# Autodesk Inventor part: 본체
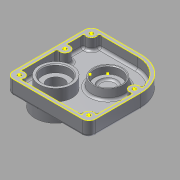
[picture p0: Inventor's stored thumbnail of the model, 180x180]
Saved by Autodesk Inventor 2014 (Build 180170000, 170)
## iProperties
Created: 2015-10
Part Number: 본체
Material: 알루미늄 6061
Document SubType Name: Modeling
Designer: youjin16
Density: 2.71 g/cm^3
Appearance: 알루미늄 - 평지
Mass: 265.675 g
Surface Area: 404.309 cm^2
Volume: 98.0352 cm^3
Author: youjin16
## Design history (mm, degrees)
sketch "스케치1"
  geometry: L1 (-42, 51.5)-(50, 51.5); L2 (50, 51.5)-(50, -43.5); L3 (42, -51.5)-(-42, -51.5); L4 (-50, -43.5)-(-50, 43.5); L5 (-50, 51.5)-(50, -51.5); L6 (50, 51.5)-(-50, -51.5); A1 r 8 centre (-42, 43.5) between (-42, 51.5) and (-50, 43.5); A2 r 8 centre (-42, -43.5) between (-50, -43.5) and (-42, -51.5); A3 r 8 centre (42, -43.5) between (42, -51.5) and (50, -43.5); 1 further point
  constraints: 12 end point, 6 point on circle, 6 point on line, 6 tangent, 3 centre point, 2 equal radius, 2 midpoint, 2 parallel, 1 horizontal, 1 perpendicular
  dimensions: "d0" = 100 distance of L5.end L6.end; "d1" = 103 distance of L6.end L5.start; "d2" = 8 radius of A1
extrude "돌출1" new body sketch "스케치1" distance "d3" = 18; taper "d4" = 0 deg
sketch "스케치2"
  geometry: L1 (50, 51.5)-(-42, 51.5) reference; L2 (-50, 43.5)-(-50, -43.5) reference; L3 (-42, -51.5)-(42, -51.5) reference; L4 (50, -43.5)-(50, 51.5) reference; L5 (-37.528, -47.5)-(37.528, -47.5); L6 (-46, -39.028)-(-46, 39.028); L7 (46, -39.028)-(46, 51.5); L8 (-37.528, 47.5)-(46, 47.5); L9 (-42, 17.5)-(-46, 17.5); L10 (-42, 5.5)-(-46, 5.5); L11 (42, 5.5)-(46, 5.5); L12 (42, 17.5)-(46, 17.5); A1 r 8 centre (-42, 43.5) between (-42, 51.5) and (-50, 43.5) reference; A2 r 8 centre (-42, -43.5) between (-50, -43.5) and (-42, -51.5) reference; A3 r 8 centre (42, -43.5) between (42, -51.5) and (50, -43.5) reference; A4 r 6 centre (-42, 43.5) between (-46, 39.028) and (-37.528, 47.5); A5 r 6 centre (-42, -43.5) between (-46, -39.028) and (-37.528, -47.5); A6 r 6 centre (42, -43.5) between (37.528, -47.5) and (46, -39.028); A7 r 6 centre (-42, 11.5) between (-42, 17.5) and (-42, 5.5); A8 r 6 centre (42, 11.5) between (42, 5.5) and (42, 17.5); 1 further point
  constraints: 16 end point, 10 point on circle, 6 perpendicular, 6 point on line, 5 centre point, 4 tangent, 3 coincident, 2 parallel, 2 vertical alignment
  dimensions: "d5" = 12 diameter of A4; "d6" = 12 diameter of A5; "d7" = 12 diameter of A6; "d8" = 4 distance between parallel lines of L3 L5; "d9" = 4 distance between parallel lines of L2 L6; "d10" = 4 distance between parallel lines of L8 L1; "d11" = 4 distance between parallel lines of L4 L7; "d16" = 12 diameter of A7; "d17" = 63 distance from line of L3 A7.centre; "d18" = 12 diameter of A8; "d19" = 63 distance from line of L3 A8.centre
extrude "돌출2" cut sketch "스케치2" distance "d12" = 4; taper "d13" = 0 deg
extrude "돌출3" join sketch "스케치2" stored distance "d20" = 4; taper "d21" = 0 deg
extrude "돌출4" join sketch "스케치2" distance "d22" = 4; taper "d23" = 0 deg
extrude "돌출5" join sketch "스케치2" distance "d24" = 4; taper "d25" = 0 deg
fillet "모깎기1" dims "d31" = 40
sketch "스케치5"
  geometry: L1 (46, 28.936)-(46, 17.5) reference; L2 (46, 17.5)-(42, 17.5) reference; L3 (42, 5.5)-(46, 5.5) reference; L4 (-37.528, 47.5)-(27.436, 47.5) reference; L5 (10, 51.5)-(-42, 51.5) reference; A1 r 6 centre (42, 11.5) between (42, 17.5) and (42, 5.5) reference; A2 r 40 centre (10, 11.5) between (27.436, 47.5) and (10, 51.5) reference; A3 r 36 centre (10, 11.5) between (10, 47.5) and (45.496, 5.5); A4 r 40 centre (10, 11.5) between (10, 51.5) and (46, 28.936); A5 r 36 centre (10, 11.5) between (45.496, 17.5) and (10, 47.5); A6 r 40 centre (10, 11.5) between (27.436, 47.5) and (10, 51.5); A7 r 40 centre (10, 11.5) between (46, 28.936) and (27.436, 47.5); A8 r 36 centre (10, 11.5) between (45.496, 5.5) and (45.688, 16.233); A9 r 36 centre (10, 11.5) between (45.688, 16.233) and (45.496, 17.5); 1 further point
  constraints: 15 point on circle, 7 centre point, 3 end point, 3 point on line, 2 coincident
  dimensions: "d32" = 72 diameter of A3
extrude "돌출7" join sketch "스케치5" stored distance "d33" = 10; taper "d34" = 0 deg
sketch "스케치6"
  geometry: C1 r 4 at (42, 43.5); C2 r 4 at (42, 11.5); C3 r 4 at (42, -43.5); C4 r 4 at (-42, -43.5); C5 r 4 at (-42, 11.5); A1 r 6 centre (42, 43.5) between (37.528, 47.5) and (46, 39.028) reference; A2 r 6 centre (42, -43.5) between (46, -39.028) and (37.528, -47.5) reference; A3 r 6 centre (42, 11.5) between (42, 17.5) and (42, 5.5) reference; A4 r 6 centre (-42, -43.5) between (-37.528, -47.5) and (-46, -39.028) reference; A5 r 6 centre (-42, 11.5) between (-42, 5.5) and (-42, 17.5) reference; 1 further point
  constraints: 5 centre point, 5 coincident
  dimensions: "d35" = 8 diameter of C1; "d36" = 8 diameter of C2; "d37" = 8 diameter of C3; "d38" = 8 diameter of C4; "d39" = 8 diameter of C5
extrude "돌출8" cut sketch "스케치6" distance "d40" = 4.4; taper "d41" = 0 deg
sketch "스케치7"
  geometry: C1 r 4 at (0, 0) reference; C2 r 4 at (0, 55) reference; C3 r 4 at (0, 87) reference; C4 r 4 at (-84, 55) reference; C5 r 4 at (-84, 0) reference; C6 r 2.25 at (0, 0); C7 r 2.25 at (0, 55); C8 r 2.25 at (0, 87); C9 r 2.25 at (-84, 55); C10 r 2.25 at (-84, 0); 1 further point
  constraints: 5 centre point, 5 coincident
  dimensions: "d42" = 4.5 diameter of C6; "d43" = 4.5 diameter of C7; "d44" = 4.5 diameter of C8; "d45" = 4.5 diameter of C9; "d46" = 4.5 diameter of C10
extrude "돌출9" cut sketch "스케치7" stored distance "d47" = 4.4; taper "d48" = 0 deg
sketch "스케치8"
  geometry: L1 (10, 51.5)-(-42, 51.5) reference; L2 (-50, 43.5)-(-50, -43.5) reference; L3 (-42, -51.5)-(42, -51.5) reference; L4 (50, -43.5)-(50, 11.5) reference; L5 (45.496, 17.5)-(42, 17.5) reference; L6 (42, 5.5)-(46, 5.5) reference; L7 (46, 5.5)-(46, -39.028) reference; L8 (37.528, -47.5)-(-37.528, -47.5) reference; L9 (-46, -39.028)-(-46, 5.5) reference; L10 (-46, 5.5)-(-42, 5.5) reference; L11 (-42, 17.5)-(-46, 17.5) reference; L12 (-46, 17.5)-(-46, 39.028) reference; L13 (-37.528, 47.5)-(10, 47.5) reference; C1 r 2.25 at (42, 11.5) reference; C2 r 2.25 at (-42, 11.5) reference; C3 r 2.25 at (-42, -43.5) reference; C4 r 2.25 at (-42, 43.5) reference; C5 r 2.25 at (42, -43.5) reference; A1 r 40 centre (10, 11.5) between (50, 11.5) and (10, 51.5) reference; A2 r 8 centre (-42, 43.5) between (-42, 51.5) and (-50, 43.5) reference; A3 r 8 centre (-42, -43.5) between (-50, -43.5) and (-42, -51.5) reference; A4 r 8 centre (42, -43.5) between (42, -51.5) and (50, -43.5) reference; A5 r 6 centre (42, 11.5) between (42, 17.5) and (42, 5.5) reference; A6 r 6 centre (42, -43.5) between (46, -39.028) and (37.528, -47.5) reference; A7 r 6 centre (-42, -43.5) between (-37.528, -47.5) and (-46, -39.028) reference; A8 r 6 centre (-42, 11.5) between (-42, 5.5) and (-42, 17.5) reference; A9 r 6 centre (-42, 43.5) between (-46, 39.028) and (-37.528, 47.5) reference; A10 r 36 centre (10, 11.5) between (45.496, 17.5) and (10, 47.5) reference; 1 further point
sketch "스케치9"
  geometry: 1 further point
sketch "스케치11"
  geometry: L1 (-50, 43.5)-(-50, -43.5) reference; L2 (-42, -51.5)-(42, -51.5) reference; C1 r 20 at (-20, -21.5); 1 further point
  constraints: 1 centre point
  dimensions: "d49" = 40 diameter of C1; "d50" = 30 distance from line of C1.centre L1; "d51" = 30 distance from line of C1.centre L2
extrude "돌출10" join sketch "스케치11" stored distance "d52" = 4.4; taper "d53" = 0 deg
sketch "스케치24"
  geometry: L1 (-37.528, 47.5)-(10, 47.5) reference; L2 (-46, 17.5)-(-46, 39.028) reference; L3 (-46, 17.5)-(-42, 17.5) reference; L4 (-42, 5.5)-(-46, 5.5) reference; L5 (-46, -39.028)-(-46, 5.5) reference; L6 (37.528, -47.5)-(-37.528, -47.5) reference; L7 (46, 5.5)-(46, -39.028) reference; L8 (46, 5.5)-(42, 5.5) reference; L9 (42, 17.5)-(45.496, 17.5) reference; C1 r 20 at (-20, -21.5) reference; C2 r 20 at (10, 11.5) reference; A1 r 36 centre (10, 11.5) between (45.496, 17.5) and (10, 47.5) reference; A2 r 6 centre (-42, 43.5) between (-46, 39.028) and (-37.528, 47.5) reference; A3 r 6 centre (-42, 11.5) between (-42, 5.5) and (-42, 17.5) reference; A4 r 6 centre (-42, -43.5) between (-37.528, -47.5) and (-46, -39.028) reference; A5 r 6 centre (42, -43.5) between (46, -39.028) and (37.528, -47.5) reference; A6 r 6 centre (42, 11.5) between (42, 17.5) and (42, 5.5) reference; 1 further point
sketch "스케치12"
  geometry: C1 r 20 at (0, 0) reference; C2 r 16 at (0, 0); 1 further point
  constraints: 1 centre point, 1 coincident
  dimensions: "d54" = 32 diameter of C2
extrude "돌출11" cut sketch "스케치12" distance "d55" = 9; taper "d56" = 0 deg
sketch "스케치13"
  geometry: C1 r 16 at (0, 0) reference; 1 further point
sketch "스케치14"
  geometry: C1 r 20 at (20, -21.5) reference; C2 r 25 at (20, -21.5); 1 further point
  constraints: 1 centre point, 1 coincident
  dimensions: "d57" = 50 diameter of C2
extrude "돌출12" join sketch "스케치14" distance "d58" = 15; taper "d59" = 0 deg
sketch "스케치15"
  geometry: C1 r 25 at (0, 0) reference; C2 r 14 at (0, 0); 1 further point
  constraints: 1 centre point, 1 coincident
  dimensions: "d60" = 28 diameter of C2
extrude "돌출13" cut sketch "스케치15" distance "d61" = 12; taper "d62" = 0 deg
sketch "스케치16"
  geometry: C1 r 14 at (0, 0) reference; C2 r 12 at (0, 0); 1 further point
  constraints: 1 centre point, 1 coincident
  dimensions: "d63" = 24 diameter of C2
extrude "돌출14" cut sketch "스케치16" distance "d64" = 2; taper "d65" = 0 deg
sketch "스케치17"
  geometry: C1 r 16 at (0, 0) reference; C2 r 10 at (0, 0); 1 further point
  constraints: 1 centre point, 1 coincident
  dimensions: "d66" = 20 diameter of C2
extrude "돌출15" cut sketch "스케치17" stored distance "d67" = 2; taper "d68" = 0 deg
sketch "스케치18"
  geometry: C1 r 25 at (0, 0) reference; A1 r 18 centre (0, 0) between (0, 18) and (18, 0); 3 further points
  constraints: 4 point on circle, 1 centre point, 1 coincident
  dimensions: "d69" = 36 diameter of A1
hole "구멍1" sketch "스케치18" at (0, 18), (18, 0), (0, -18), (-18, 0) diameter "d70" = 2.459; stored, may be unused: countersink angle "d74" = 90 deg, drill point angle "d76" = 118 deg; dims "d71" = 8, "d72" = 4, "d73" = 2, "d75" = 10
sketch "스케치19"
  geometry: 1 further point
node "작업 평면2"
node "작업 평면3"
node "작업 평면4"
sketch "스케치20"
  geometry: 1 further point
node "작업 평면5"
sketch "스케치23"
  geometry: 1 further point
node "작업 평면6"
sketch "스케치25"
  geometry: 1 further point
node "작업 평면7"
sketch "스케치26"
  geometry: 1 further point
sketch "스케치27"
  geometry: L1 (45.496, 17.5)-(42, 17.5) reference; L2 (42, 5.5)-(46, 5.5) reference; L3 (46, 5.5)-(46, -39.028) reference; L4 (37.528, -47.5)-(-37.528, -47.5) reference; L5 (-46, -39.028)-(-46, 5.5) reference; L6 (-46, 5.5)-(-42, 5.5) reference; L7 (-42, 17.5)-(-46, 17.5) reference; L8 (-46, 17.5)-(-46, 39.028) reference; L9 (-37.528, 47.5)-(10, 47.5) reference; C1 r 20 at (10, 11.5); C2 r 20 at (-20, -21.5) reference; C3 r 20 at (-20, -21.5) reference; A1 r 6 centre (42, 11.5) between (42, 17.5) and (42, 5.5) reference; A2 r 6 centre (42, -43.5) between (46, -39.028) and (37.528, -47.5) reference; A3 r 6 centre (-42, -43.5) between (-37.528, -47.5) and (-46, -39.028) reference; A4 r 6 centre (-42, 11.5) between (-42, 5.5) and (-42, 17.5) reference; A5 r 6 centre (-42, 43.5) between (-46, 39.028) and (-37.528, 47.5) reference; A6 r 36 centre (10, 11.5) between (45.496, 17.5) and (10, 47.5) reference; 1 further point
  constraints: 1 centre point, 1 coincident
  dimensions: "d91" = 40 diameter of C1
extrude "돌출19" cut sketch "스케치27" distance "d92" = 14; taper "d93" = 0 deg
sketch "스케치28"
  geometry: C1 r 20 at (10, 11.5); A1 r 36 centre (10, 11.5) between (45.496, 17.5) and (10, 47.5) reference; 1 further point
  constraints: 1 centre point, 1 coincident
  dimensions: "d94" = 40 diameter of C1
extrude "돌출20" join sketch "스케치28" distance "d95" = 11; taper "d96" = -10 deg
node "작업 평면8"
sketch "스케치29"
  geometry: C1 r 18.06 at (0, 0) reference; C2 r 16 at (0, 0); 1 further point
  constraints: 1 centre point, 1 coincident
  dimensions: "d98" = 32 diameter of C2
extrude "돌출21" cut sketch "스케치29" distance "d99" = 9; taper "d100" = 0 deg
sketch "스케치30"
  geometry: C1 r 16 at (0, 0) reference; C2 r 11 at (0, 0); 1 further point
  constraints: 1 centre point, 1 coincident
  dimensions: "d101" = 22 diameter of C2
extrude "돌출22" cut sketch "스케치30" distance "d102" = 2; taper "d103" = 0 deg
node "작업 평면9"
sketch "스케치32"
  geometry: 1 further point
sketch "스케치33"
  geometry: L1 (50, 43.5)-(50, -43.5) reference; L2 (-10, 51.5)-(42, 51.5) reference; 2 further points
  constraints: 1 other
  dimensions: "d107" = 40 distance from line of L1 point (10, 31.5); "d108" = 20 distance from line of L2 point (10, 31.5)
feature "엠보싱1" sketch "스케치33" dims "d109" = 0.5, "d110" = 0
fillet "모깎기4" dims "d113" = 3
node "작업 평면10"
fillet "모깎기5" dims "d115" = 3
fillet "모깎기6" dims "d116" = 0.3
chamfer "모따기1" distance "d117" = 1; stored, may be unused: second distance "d118" = 2, angle "d119" = 45 deg
fillet "모깎기7" dims "d120" = 3
fillet "모깎기8" dims "d121" = 3
chamfer "모따기2" distance "d126" = 1; stored, may be unused: second distance "d127" = 2, angle "d128" = 45 deg
chamfer "모따기3" distance "d130" = 1; stored, may be unused: second distance "d131" = 2, angle "d132" = 45 deg
fillet "모깎기10" dims "d133" = 3
node "솔리드1"
